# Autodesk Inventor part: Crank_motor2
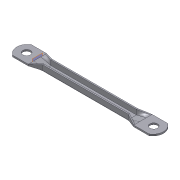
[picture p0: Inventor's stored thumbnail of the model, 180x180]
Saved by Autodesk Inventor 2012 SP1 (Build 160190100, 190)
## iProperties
Created: 2006-03
Part Number: Crank_motor2
Document SubType Name: Modeling
Material: Stainless Steel, 440C
Mass: 59.5804 g
Surface Area: 96.204 cm^2
Volume: 7.6878 cm^3
Density: 7.75 g/cm^3
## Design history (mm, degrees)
sketch "Sketch1"
  geometry: L1 (0, 0)-(0, 1.6); L2 (0, 1.6)-(4.6, 1.6); L3 (4.6, 1.6)-(4.6, 8); L4 (4.6, 8)-(6.2, 8); L5 (6.2, 8)-(6.2, 1.5); L6 (4.7, 0)-(0, 0); L7 (0, 10.493)-(0, -1.142) reference; L8 (-4.6, 1.6)-(-4.6, 8); L9 (-4.6, 8)-(-6.2, 8); L10 (-6.2, 8)-(-6.2, 1.5); L11 (0, 1.6)-(-4.6, 1.6); L12 (-4.7, 0)-(0, 0); A1 r 1.5 centre (4.7, 1.5) between (4.7, 0) and (6.2, 1.5); A2 r 1.5 centre (-4.7, 1.5) between (-6.2, 1.5) and (-4.7, 0)
  constraints: 22 end point, 6 symmetric about line, 4 parallel, 4 point on circle, 2 centre point, 2 perpendicular, 2 tangent, 1 vertical, 1 other
  dimensions: "d1" = 4.6 distance between parallel lines of L3 L1; "d2" = 8 distance between parallel lines of L6 L4; "d3" = 1.6 distance between parallel lines of L5 L3; "d4" = 1.5 radius of A1
extrude "Extrusion1" new body sketch "Sketch1" distance "d5" = 55.6; taper "d6" = 0 deg
workplane "Work Plane1"
sketch "Sketch2"
  geometry: L1 (-0.8, 0)-(10.4, 0) reference; L2 (3, 12)-(5, 12); L3 (5, 12)-(5, -12); L4 (5, -12)-(3, -12); L5 (3, -12)-(3, 12); L6 (3, 12)-(5, -12); L7 (1.5, 6.2)-(8, 6.2) reference; L8 (8, -6.2)-(1.5, -6.2) reference; L9 (0, -4.7)-(0, 4.7) reference; 2 further points
  constraints: 10 end point, 2 parallel, 1 horizontal, 1 midpoint, 1 perpendicular, 1 point on line
  dimensions: "d8" = 4 distance from line of point (4, 0) L9; "d9" = 2 distance of L2.start L2.end; "d10" = 24 distance of L2.end L3.end
loft "Loft1" sketch "Sketch2" dims "d11" = 0, "d12" = 90 deg, "d13" = 0, "d14" = 90 deg
  node "Edges1"
sketch "Sketch3"
  geometry: L1 (2, 12.374)-(2, 18.469) reference; L2 (2, 19.993)-(0, 19.993) reference; L3 (2, 18.469)-(2, 19.993) reference; L4 (2, 3.612)-(2, 12.374) reference; L5 (2, -2.483)-(2, 3.612) reference; L6 (2, -4.007)-(2, -2.483) reference; L7 (0, -4.007)-(2, -4.007) reference; L8 (0, 0)-(0, -4.007) reference; L9 (0, 15.986)-(0, 0) reference; L10 (0, 19.993)-(0, 15.986) reference; 1 further point
extrude "Extrusion2" join sketch "Sketch3" distance "d15" = 20; taper "d16" = 0 deg
sketch "Sketch4"
  geometry: L1 (-8.86, 12)-(115.18, 12) reference; L2 (0, 24)-(0, 0); A1 r 14 centre (7.211, 12) between (0, 24) and (0, 0); 1 further point
  constraints: 3 point on circle, 2 end point, 1 centre point, 1 perpendicular, 1 point on line
  dimensions: "d17" = 14 radius of A1
extrude "Extrusion3" join sketch "Sketch4" stored distance "d18" = 20; taper "d19" = 0 deg
sketch "Sketch5"
  geometry: L1 (-36.328, 4.381)-(97.217, 4.381) reference; L2 (0, 12.374)-(0, -3.612) reference; C1 r 5 at (-14, 4.381); 1 further point
  constraints: 1 centre point, 1 point on line
  dimensions: "d20" = 10 diameter of C1; "d21" = 14 distance from line of C1.centre L2
extrude "Extrusion4" cut sketch "Sketch5" stored distance "d22" = 20; taper "d23" = 0 deg
mirror "Mirror1"
body "Solid1"
other parameters: "d7" = 13
